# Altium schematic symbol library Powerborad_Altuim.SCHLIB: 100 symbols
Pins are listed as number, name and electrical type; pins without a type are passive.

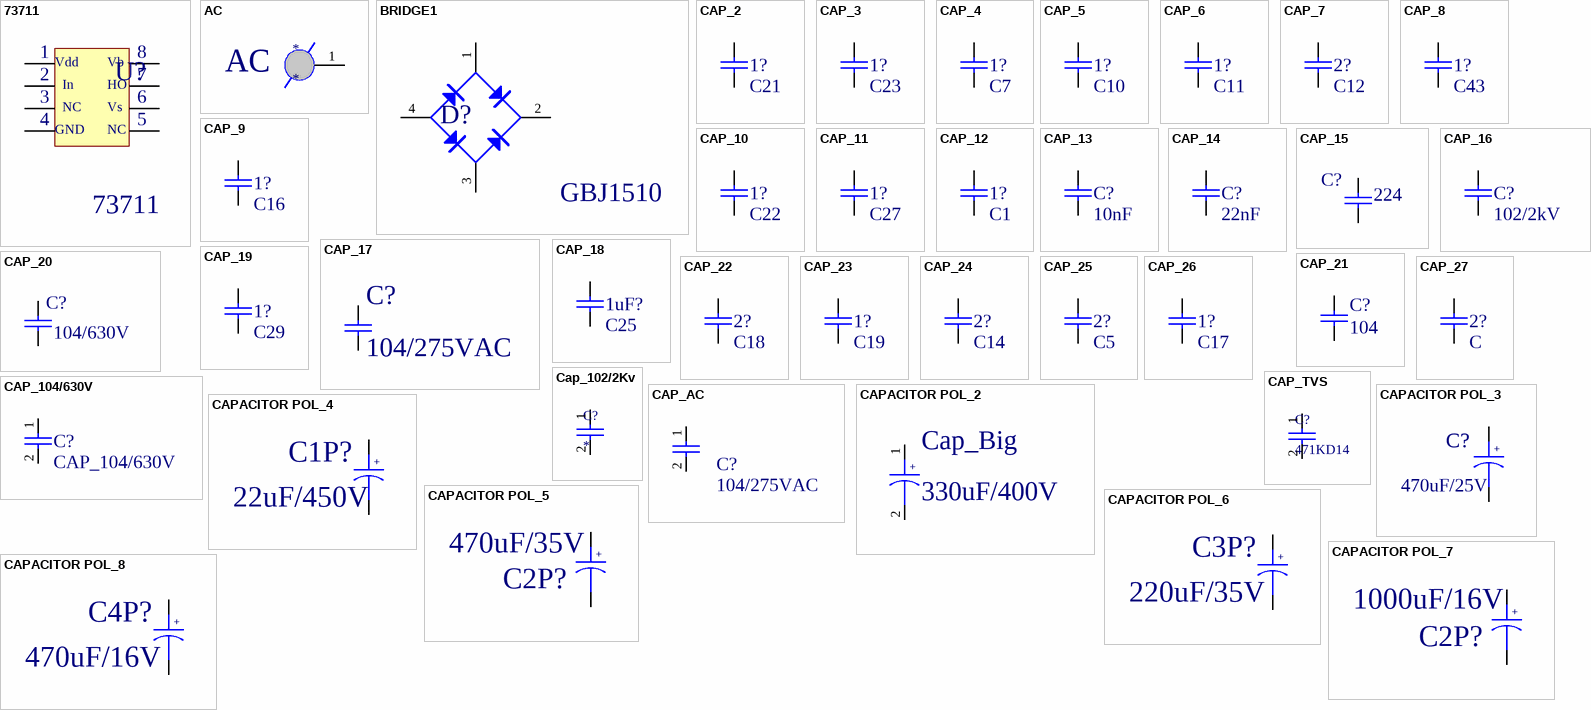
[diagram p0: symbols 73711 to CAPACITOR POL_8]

## 73711
designator U?
footprint 73711
pins: 1, 2, 3, 4, 5, 6, 7, 8

## AC
designator *
footprint AC
pins: 1

## BRIDGE1
designator D?, comment GBJ1510
Diode Bridge
footprint Bridge
pins: 1 AC, 2 V+, 3 AC, 4 V-

## CAP_2
designator 1?, comment C21
Capacitor
pins: 1, 2

## CAP_3
designator 1?, comment C23
Capacitor
pins: 1, 2

## CAP_4
designator 1?, comment C7
Capacitor
pins: 1, 2

## CAP_5
designator 1?, comment C10
Capacitor
pins: 1, 2

## CAP_6
designator 1?, comment C11
Capacitor
pins: 1, 2

## CAP_7
designator 2?, comment C12
Capacitor
pins: 1, 2

## CAP_8
designator 1?, comment C43
Capacitor
pins: 1, 2

## CAP_9
designator 1?, comment C16
Capacitor
pins: 1, 2

## CAP_10
designator 1?, comment C22
Capacitor
pins: 1, 2

## CAP_11
designator 1?, comment C27
Capacitor
pins: 1, 2

## CAP_12
designator 1?, comment C1
Capacitor
pins: 1, 2

## CAP_13
designator C?, comment 10nF
Capacitor
pins: 1, 2

## CAP_14
designator C?, comment 22nF
Capacitor
pins: 1, 2

## CAP_15
designator C?, comment 224
Capacitor
pins: 1, 2

## CAP_16
designator C?, comment 102/2kV
Capacitor
pins: 1, 2

## CAP_17
designator C?, comment 104/275VAC
Capacitor
pins: 1, 2

## CAP_18
designator 1uF?, comment C25
Capacitor
pins: 1, 2

## CAP_19
designator 1?, comment C29
Capacitor
pins: 1, 2

## CAP_20
designator C?, comment 104/630V
Capacitor
pins: 1, 2

## CAP_21
designator C?, comment 104
Capacitor
pins: 1, 2

## CAP_22
designator 2?, comment C18
Capacitor
pins: 1, 2

## CAP_23
designator 1?, comment C19
Capacitor
pins: 1, 2

## CAP_24
designator 2?, comment C14
Capacitor
pins: 1, 2

## CAP_25
designator 2?, comment C5
Capacitor
pins: 1, 2

## CAP_26
designator 1?, comment C17
Capacitor
pins: 1, 2

## CAP_27
designator 2?, comment C
Capacitor
pins: 1, 2

## Cap_102/2Kv
designator C?
footprint CAP_102_2KV
pins: 1, 2

## CAP_104/630V
designator C?
Capacitor
footprint 104/630V
pins: 1, 2

## CAP_AC
designator C?, comment 104/275VAC
Capacitor AC 104/275VAC
footprint CAP_AC (104/275VAC)
pins: 1, 2

## CAP_TVS
designator C?, comment 471KD14
footprint CAP_TR
pins: 1, 2

## CAPACITOR POL_2
designator Cap_Big, comment 330uF/400V
Capacitor
footprint CAP_B
pins: 1, 2

## CAPACITOR POL_3
designator C?, comment 470uF/25V
Capacitor
pins: 1, 2

## CAPACITOR POL_4
designator C1P?, comment 22uF/450V
Capacitor
pins: 1, 2

## CAPACITOR POL_5
designator C2P?, comment 470uF/35V
Capacitor
pins: 1, 2

## CAPACITOR POL_6
designator C3P?, comment 220uF/35V
Capacitor
pins: 1, 2

## CAPACITOR POL_7
designator C2P?, comment 1000uF/16V
Capacitor
pins: 1, 2

## CAPACITOR POL_8
designator C4P?, comment 470uF/16V
Capacitor
pins: 1, 2

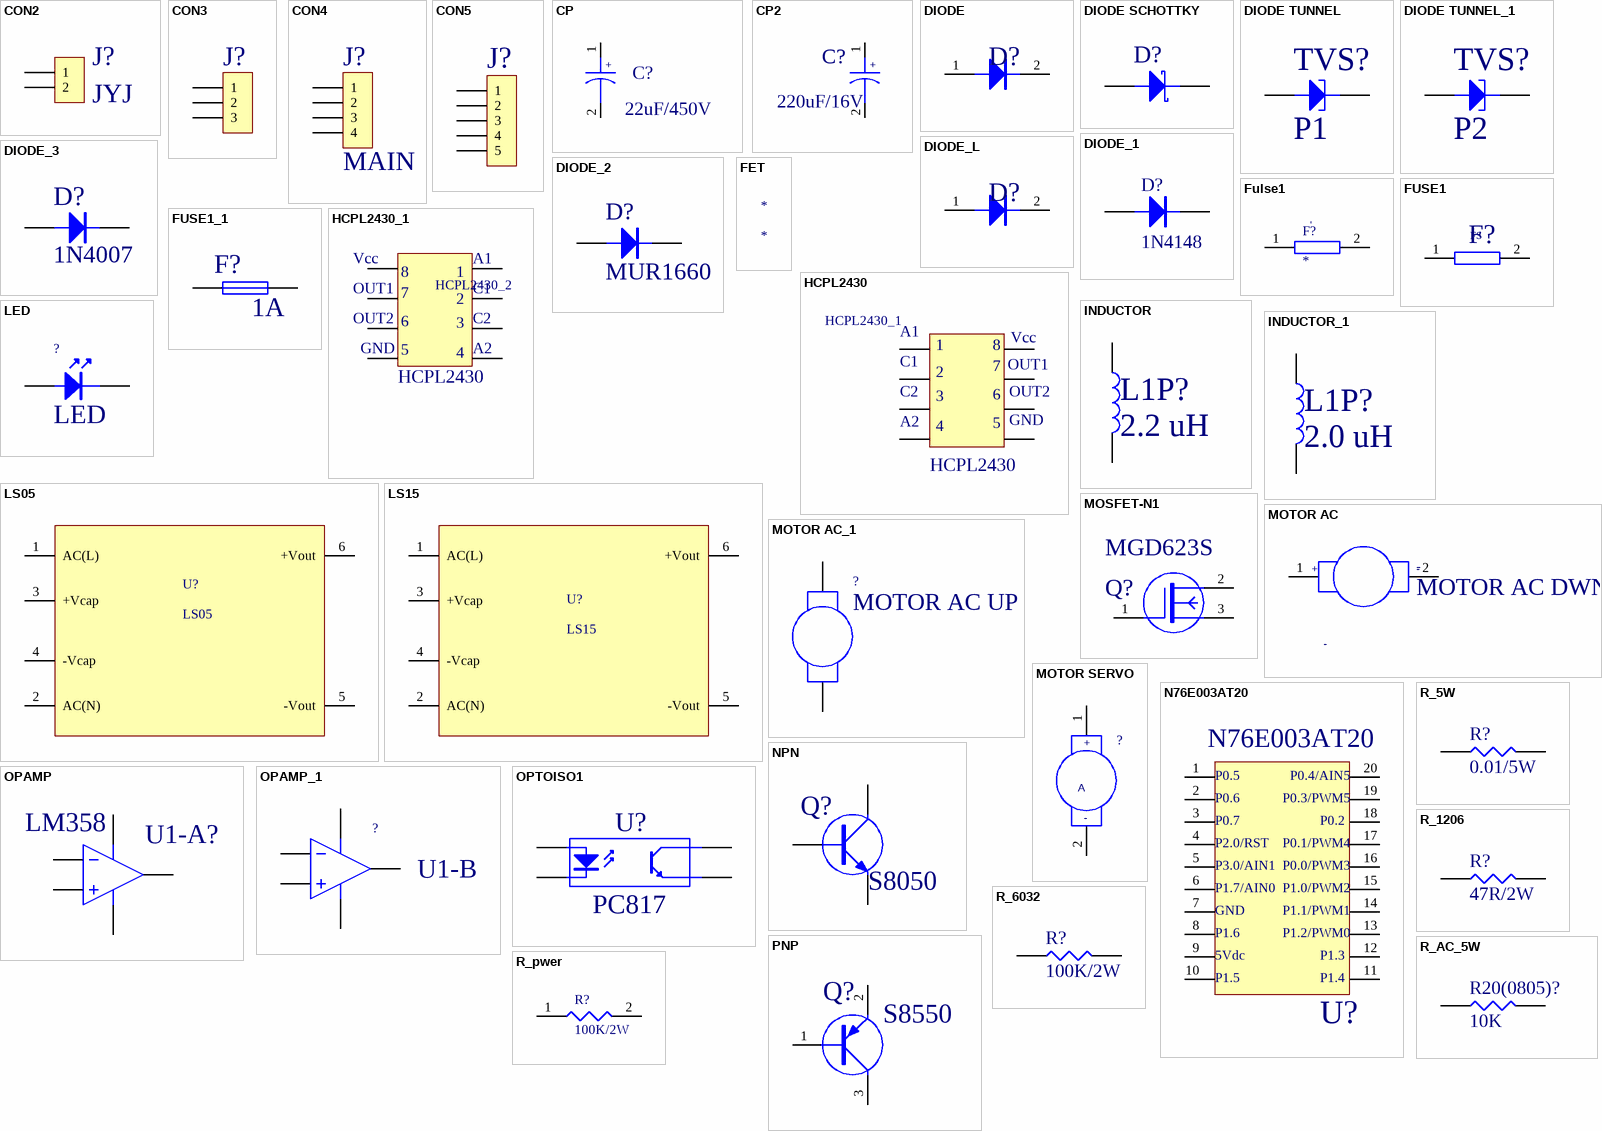
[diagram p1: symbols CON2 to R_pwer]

## CON2
designator J?, comment JYJ
Connector
pins: 1, 2

## CON3
designator J?
Connector
pins: 1, 2, 3

## CON4
designator J?, comment MAIN
Connector
pins: 1, 2, 3, 4

## CON5
designator J?
Connector
pins: 1, 2, 3, 4, 5

## CP
designator C?, comment 22uF/450V
Capacitor 22uF/450V
footprint CP
pins: 1, 2

## CP2
designator C?, comment 220uF/16V
Capacitor
footprint CP212
pins: 1, 2

## DIODE
designator D?
Diode
footprint DIODE
pins: 1 A, 2 K

## DIODE SCHOTTKY
designator D?
Schottky Diode
pins: 1 A, 2 K

## DIODE TUNNEL
designator TVS?, comment P1
Diode Tunnel
pins: 1 A, 2 K

## DIODE TUNNEL_1
designator TVS?, comment P2
Diode Tunnel
pins: 1 A, 2 K

## DIODE_1
designator D?, comment 1N4148
Diode
pins: 1 A, 2 K

## DIODE_2
designator D?, comment MUR1660
Diode
pins: 1 A, 2 K

## DIODE_3
designator D?, comment 1N4007
Diode
pins: 1 A, 2 K

## DIODE_L
designator D?
Diode
footprint Diode_L
pins: 1 A, 2 K

## FET
designator *

## Fulse1
designator F?
footprint Fulse_1
pins: 1, 2

## FUSE1
designator F?
Fuse
footprint FULSE
pins: 1, 2

## FUSE1_1
designator F?, comment 1A
Fuse
pins: 1, 2

## HCPL2430
designator HCPL2430_1
footprint HCPL2430
pins: 1, 2, 3, 4, 5, 6, 7, 8

## HCPL2430_1
designator HCPL2430_2
footprint HCPL2430
pins: 1, 2, 3, 4, 5, 6, 7, 8

## INDUCTOR
designator L1P?, comment 2.2 uH
pins: 1, 2

## INDUCTOR_1
designator L1P?, comment 2.0 uH
pins: 1, 2

## LED
designator ?
pins: A 1, K 2

## LS05
designator U?
footprint LS05
pins: 1 AC(L), 2 AC(N), 3 +Vcap, 4 -Vcap, 5 -Vout, 6 +Vout

## LS15
designator U?
footprint LS15
pins: 1 AC(L), 2 AC(N), 3 +Vcap, 4 -Vcap, 5 -Vout, 6 +Vout

## MOSFET-N1
designator Q?, comment MGD623S
footprint FET
pins: 1 G, 2 D, 3 S

## MOTOR AC
designator -, comment MOTOR AC DWN
footprint MOTO
pins: 1, 2

## MOTOR AC_1
designator ?, comment MOTOR AC UP
pins: 1, 2

## MOTOR SERVO
designator ?
footprint Servo
pins: 1 +, 2 -

## N76E003AT20
designator U?
footprint N76
pins: 1, 2, 3, 4, 5, 6, 7, 8, 9, 10, 11, 12, 13, 14, 15, 16, 17, 18, 19, 20

## NPN
designator Q?, comment S8050
NPN Transistor
pins: 1 B, 2 C, 3 E

## OPAMP
designator U1-A?, comment LM358
Operational Amplifier
pins: 1 IN-, 2 IN+, 3 OUT, 4 V+, 5 V-

## OPAMP_1
designator ?, comment U1-B
Operational Amplifier
pins: 1 IN-, 2 IN+, 3 OUT, 4 V+, 5 V-

## OPTOISO1
designator U?, comment PC817
Optoisolator
pins: 1 A, 2 K, 3 C, 4 E

## PNP
designator Q?, comment S8550
PNP Transistor
pins: 1 B, 2 E, 3 C

## R_5W
designator R?, comment 0.01/5W
footprint 0.01/5W
pins: 1, 2

## R_1206
designator R?, comment 47R/2W
footprint 1206
pins: 1, 2

## R_6032
designator R?, comment 100K/2W
footprint 6032
pins: 1, 2

## R_AC_5W
designator R20(0805)?, comment 10K
footprint R_AC_5W
pins: 1, 2

## R_pwer
designator R?, comment 100K/2W
footprint 1206
pins: 1, 2

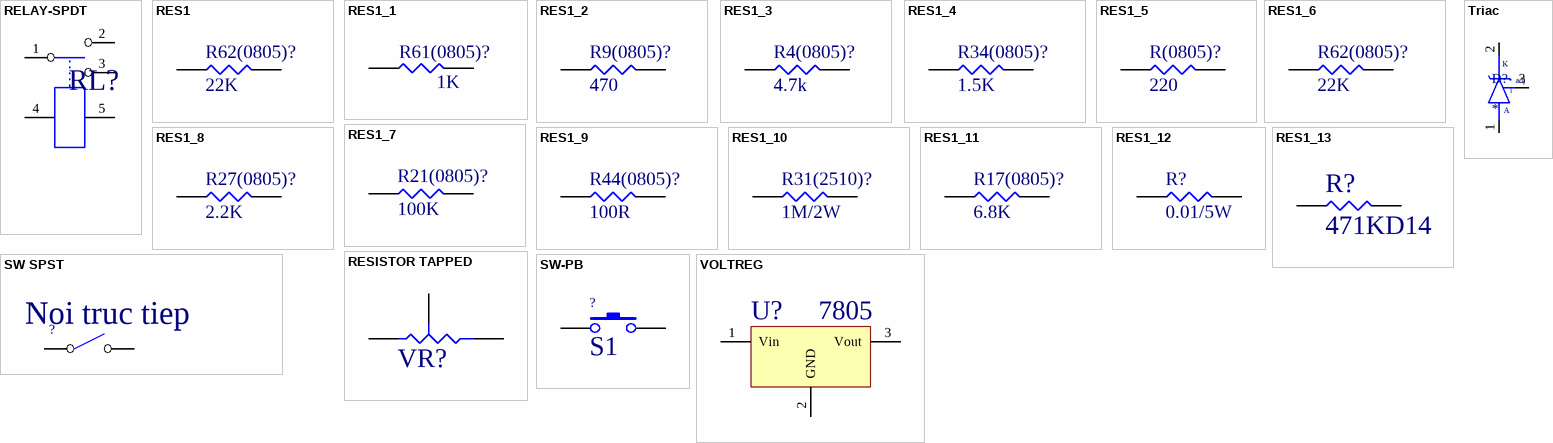
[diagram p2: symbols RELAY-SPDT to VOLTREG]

## RELAY-SPDT
designator RL?
footprint Relay
pins: 1, 2, 3, 4, 5

## RES1
designator R62(0805)?, comment 22K
pins: 1, 2

## RES1_1
designator R61(0805)?, comment 1K
pins: 1, 2

## RES1_2
designator R9(0805)?, comment 470
pins: 1, 2

## RES1_3
designator R4(0805)?, comment 4.7k
pins: 1, 2

## RES1_4
designator R34(0805)?, comment 1.5K
pins: 1, 2

## RES1_5
designator R(0805)?, comment 220
pins: 1, 2

## RES1_6
designator R62(0805)?, comment 22K
pins: 1, 2

## RES1_7
designator R21(0805)?, comment 100K
pins: 1, 2

## RES1_8
designator R27(0805)?, comment 2.2K
pins: 1, 2

## RES1_9
designator R44(0805)?, comment 100R
pins: 1, 2

## RES1_10
designator R31(2510)?, comment 1M/2W
pins: 1, 2

## RES1_11
designator R17(0805)?, comment 6.8K
pins: 1, 2

## RES1_12
designator R?, comment 0.01/5W
pins: 1, 2

## RES1_13
designator R?, comment 471KD14
pins: 1, 2

## RESISTOR TAPPED
designator VR?
pins: 1 A, 2 B, 3 TAP

## SW SPST
designator ?, comment Noi truc tiep
pins: 1 COMMON, 2 NO

## SW-PB
designator ?, comment S1
pins: 1, 2

## Triac
designator D?
MUR1660
footprint Triac
pins: 1 A, 2 K, 3 adj

## VOLTREG
designator U?, comment 7805
footprint TO220H
pins: 1 Vin, 2 GND, 3 Vout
